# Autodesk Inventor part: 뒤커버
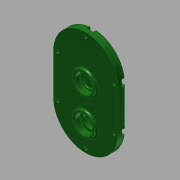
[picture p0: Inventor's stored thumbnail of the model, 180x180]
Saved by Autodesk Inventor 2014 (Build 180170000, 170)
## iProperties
Created: 2016-12
Part Number: 뒤커버
Material: 일반
Document SubType Name: Modeling
Designer: mduedu
Density: 1 g/cm^3
Appearance: 매끄러움 - 짙은 산림 녹색
Mass: 86.8849 g
Surface Area: 237.575 cm^2
Volume: 86.8849 cm^3
Author: mduedu
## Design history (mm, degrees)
sketch "스케치1"
  geometry: L1 (40, -25)-(40, 25); L2 (-40, 25)-(-40, -25); L3 (-40, -25)-(40, 25); L4 (40, -25)-(-40, 25); A1 r 40 centre (0, 25) between (40, 25) and (-40, 25); A2 r 40 centre (0, -25) between (-40, -25) and (40, -25); 1 further point
  constraints: 8 end point, 4 point on circle, 4 tangent, 2 centre point, 2 midpoint, 1 parallel, 1 vertical
  dimensions: "d0" = 130 dimension on A2 A1; "d2" = 80 distance between parallel lines of L1 L2
extrude "돌출1" new body sketch "스케치1" distance "d3" = 10; taper "d4" = 0 deg
sketch "스케치2"
  geometry: C1 r 14 at (0, 11); 1 further point
  constraints: 1 centre point, 1 vertical alignment
  dimensions: "d5" = 28 diameter of C1; "d6" = 11 distance of C1.centre point (0, 0)
extrude "돌출2" join sketch "스케치2" distance "d7" = 3; taper "d8" = 0 deg
sketch "스케치3"
  geometry: C1 r 14 at (0, -33.1); C2 r 14 at (0, 11) reference; 1 further point
  constraints: 1 centre point, 1 vertical alignment
  dimensions: "d9" = 28 diameter of C1; "d69" = 44.1 distance of C1.centre C2.centre
extrude "돌출3" join sketch "스케치3" distance "d11" = 3; taper "d12" = 0 deg
hole "구멍1" diameter "d15" = 22; stored, may be unused: countersink angle "d19" = 90 deg, drill point angle "d21" = 0 deg; dims "d13" = 10, "d14" = 10, "d16" = 6, "d17" = 4, "d18" = 2, "d20" = 7
hole "구멍2" diameter "d24" = 18; stored, may be unused: countersink angle "d28" = 90 deg, drill point angle "d30" = 0 deg; dims "d22" = 10, "d23" = 10, "d25" = 6, "d26" = 4, "d27" = 2, "d29" = 1
hole "구멍3" diameter "d33" = 22; stored, may be unused: countersink angle "d37" = 90 deg, drill point angle "d39" = 0 deg; dims "d31" = 10, "d32" = 10, "d34" = 6, "d35" = 4, "d36" = 2, "d38" = 7
sketch "스케치4"
  geometry: C1 r 14 at (0, -33.1) reference; C2 r 18 at (0, -33.1); 1 further point
  constraints: 1 centre point, 1 coincident
  dimensions: "d40" = 36 diameter of C2
extrude "돌출4" join sketch "스케치4" distance "d41" = 4; taper "d42" = 0 deg
hole "구멍4" diameter "d45" = 22; stored, may be unused: countersink angle "d49" = 90 deg, drill point angle "d51" = 0 deg; dims "d43" = 10, "d44" = 10, "d46" = 6, "d47" = 4, "d48" = 2, "d50" = 7
hole "구멍5" diameter "d54" = 15; stored, may be unused: countersink angle "d58" = 90 deg, drill point angle "d60" = 0 deg; dims "d52" = 10, "d53" = 10, "d55" = 6, "d56" = 4, "d57" = 2, "d59" = 7
fillet "모깎기1" dims "d61" = 0.3
fillet "모깎기2" dims "d62" = 2
chamfer "모따기1" distance "d63" = 1; stored, may be unused: second distance "d64" = 2, angle "d65" = 45 deg
fillet "모깎기3" dims "d66" = 2
fillet "모깎기4" dims "d67" = 2
fillet "모깎기5" dims "d68" = 2
sketch "스케치5"
  geometry: L1 (-40, 25)-(-40, -25) reference; L2 (40, -25)-(40, 25) reference; L3 (35, 25)-(35, -25); L4 (-35, -25)-(-35, 25); A1 r 40 centre (0, 25) between (40, 25) and (-40, 25) reference; A2 r 40 centre (0, -25) between (-40, -25) and (40, -25) reference; A3 r 35 centre (0, 25) between (35, 25) and (-35, 25); A4 r 35 centre (0, -25) between (-35, -25) and (35, -25); 2 further points
  constraints: 5 point on circle, 4 end point, 2 centre point, 1 vertical alignment, 3 other
  dimensions: "d70" = 5 distance between parallel lines of L2 L3
sketch "스케치6"
  geometry: 1 further point
hole "구멍6" sketch "스케치6" at (0, 60) diameter "d71" = 4.5; stored, may be unused: countersink angle "d75" = 90 deg, drill point angle "d77" = 0 deg; dims "d72" = 6, "d73" = 8, "d74" = 4.6, "d76" = 8
sketch "스케치7"
  geometry: L1 (-4, 0)-(4, 0); L2 (4, 0)-(4, 5); L3 (4, 5)-(-4, 5); L4 (-4, 5)-(-4, 0); C1 r 2.25 at (0, 0) reference; A1 r 40 centre (0, -35) between (40, -35) and (-40, -35) reference; 2 further points
  constraints: 8 end point, 2 parallel, 2 vertical, 1 horizontal, 1 horizontal alignment, 1 perpendicular, 1 tangent, 1 other
extrude "돌출5" cut sketch "스케치7" stored distance "d80" = 10; taper "d81" = 0 deg
fillet "모깎기6" dims "d82" = 0.3
fillet "모깎기7" dims "d83" = 0.3
node "솔리드1"
pattern_linear "직사각형 패턴1"
node "투영된 루프1"
